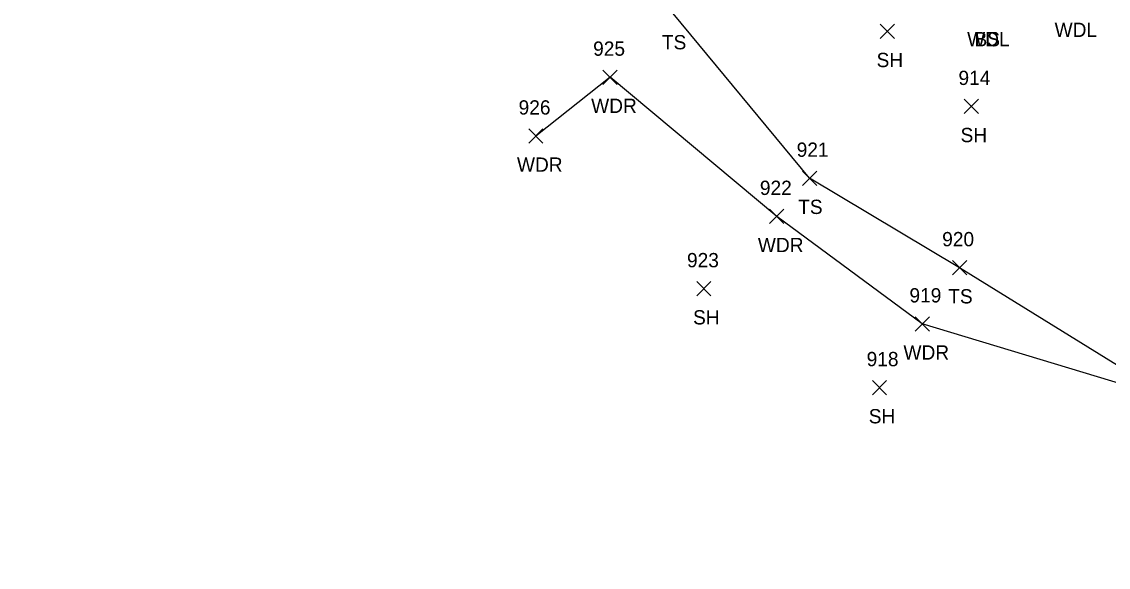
# Model space of a CAD drawing. Extents: x 1879695 to 1880991, y 836466 to 845172.
# Drawn here: x 1879839.4 to 1879991.4, y 844084.6 to 844161 of the extents above; entities that cross this region are included whole.
import ezdxf

# ---------------------------------------------------------------- set-up
doc = ezdxf.new("R2010")
doc.units = 0
for name, color, linetype in [('L_A', 7, 'Continuous'), ('L_I', 7, 'Continuous'), ('L_TIC', 7, 'Continuous'), ('LAWA', 7, 'Continuous'), ('LELB', 7, 'Continuous')]:
    doc.layers.add(name, color=color, linetype=linetype)

msp = doc.modelspace()

# ---------------------------------------------------------------- linework, layer by layer
at = {"layer": 'L_TIC'}
for points in [[(1879959.52, 844158.6), (1879961.52, 844160.6)], [(1879961.52, 844158.6), (1879959.52, 844160.6)], [(1879920.71, 844152.19), (1879922.71, 844154.19)], [(1879922.71, 844152.19), (1879920.71, 844154.19)], [(1879971.27, 844148.1), (1879973.27, 844150.1)], [(1879973.27, 844148.1), (1879971.27, 844150.1)], [(1879910.33, 844143.96), (1879912.33, 844145.96)], [(1879912.33, 844143.96), (1879910.33, 844145.96)], [(1879948.63, 844138.05), (1879950.63, 844140.05)], [(1879950.63, 844138.05), (1879948.63, 844140.05)], [(1879944.04, 844132.71), (1879946.04, 844134.71)], [(1879946.04, 844132.71), (1879944.04, 844134.71)], [(1879969.63, 844125.53), (1879971.63, 844127.53)], [(1879971.63, 844125.53), (1879969.63, 844127.53)], [(1879933.84, 844122.59), (1879935.84, 844124.59)], [(1879935.84, 844122.59), (1879933.84, 844124.59)], [(1879964.41, 844117.67), (1879966.41, 844119.67)], [(1879966.41, 844117.67), (1879964.41, 844119.67)], [(1879958.42, 844108.75), (1879960.42, 844110.75)], [(1879960.42, 844108.75), (1879958.42, 844110.75)]]:
    msp.add_lwpolyline(points, dxfattribs=at)
at = {"layer": 'LAWA'}
msp.add_lwpolyline([(1880039.21, 844084.61), (1880000.41, 844108.08), (1879965.41, 844118.67), (1879945.04, 844133.71), (1879921.71, 844153.19), (1879911.33, 844144.96)], dxfattribs=at)
at = {"layer": 'LELB'}
msp.add_lwpolyline([(1880000.41, 844108.08), (1879970.63, 844126.53), (1879949.63, 844139.05), (1879930.57, 844162.09), (1879904.28, 844177.57), (1879891.68, 844181.68), (1879866.82, 844218.96), (1879857.04, 844216.58), (1879839.4, 844202.83)], dxfattribs=at)

# ---------------------------------------------------------------- texts
at = {"layer": 'L_A'}
for s, p in [('WDL', (1879983.92, 844158.82)), ('TS', (1879928.97, 844157.09)), ('WDL', (1879971.68, 844157.51)), ('BS', (1879972.71, 844157.51)), ('SH', (1879959.01, 844154.6)), ('WDR', (1879919.07, 844148.19)), ('SH', (1879970.76, 844144.1)), ('WDR', (1879908.69, 844139.96)), ('TS', (1879948.04, 844134.05)), ('WDR', (1879942.4, 844128.71)), ('TS', (1879969.04, 844121.53)), ('SH', (1879933.33, 844118.59)), ('WDR', (1879962.77, 844113.67)), ('SH', (1879957.91, 844104.75))]:
    msp.add_text(s, height=2, dxfattribs=at).set_placement(p)
at = {"layer": 'L_I'}
for s, p in [('925', (1879919.35, 844156.19)), ('914', (1879970.47, 844152.1)), ('926', (1879908.92, 844147.96)), ('921', (1879947.83, 844142.05)), ('922', (1879942.68, 844136.71)), ('920', (1879968.19, 844129.53)), ('923', (1879932.48, 844126.59)), ('919', (1879963.61, 844121.67)), ('918', (1879957.62, 844112.75))]:
    msp.add_text(s, height=2, dxfattribs=at).set_placement(p)

doc.saveas('drawing.dxf')
